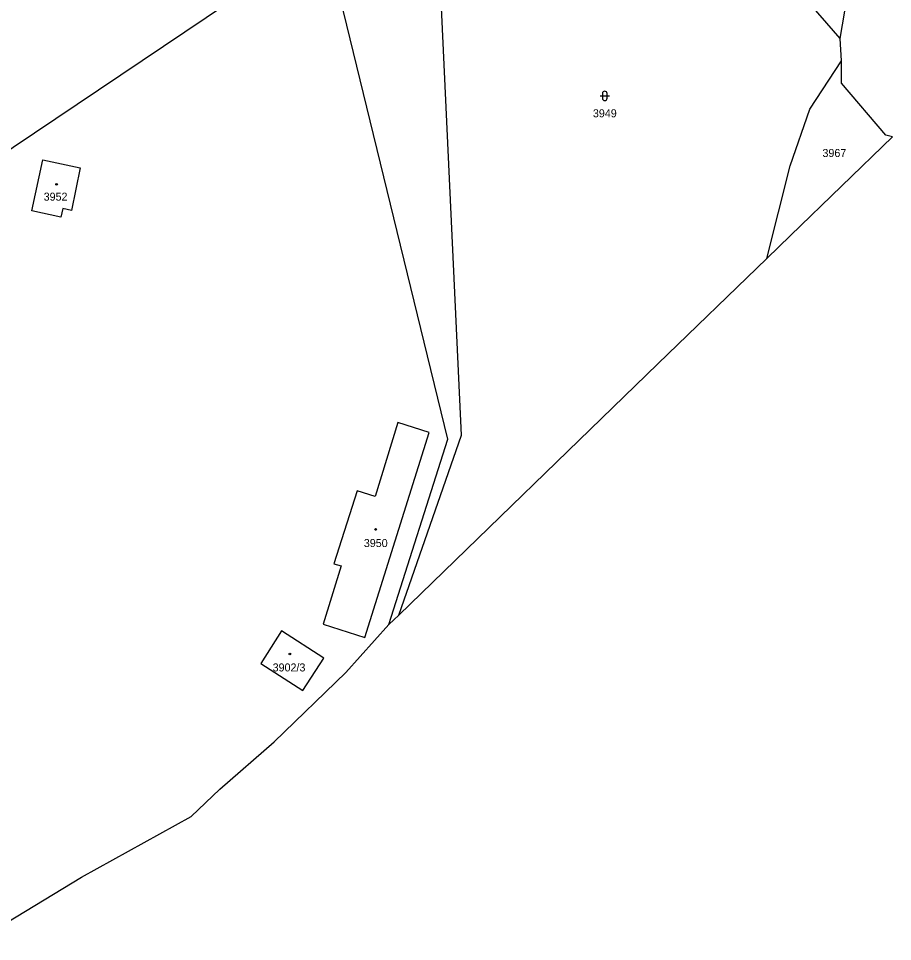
# Model space of a CAD drawing. Extents: x -869103 to -863415, y -1015889 to -1012477.
# Drawn here: x -867451.5 to -867266, y -1015422.4 to -1015226.4 of the extents above; entities that cross this region are included whole.
import ezdxf

# ---------------------------------------------------------------- set-up
doc = ezdxf.new("R2010")
doc.units = 0
for name, color, linetype in [('Hranice katastralního území', 7, 'Continuous'), ('Hranice parcel', 7, 'Continuous'), ('Parcelní čísla', 7, 'Continuous'), ('Poz předměty', 7, 'Continuous'), ('Značky budov', 7, 'Continuous'), ('Značky kultur', 7, 'Continuous')]:
    doc.layers.add(name, color=color, linetype=linetype)

msp = doc.modelspace()

# ---------------------------------------------------------------- linework, layer by layer
at = {"layer": 'Hranice katastralního území'}
for p, q in [((-867277.08, -1015230.7), (-867274.22, -1015213.59)), ((-867276.8, -1015235.41), (-867277.08, -1015230.7)), ((-867287.62, -1015272.48), (-867266, -1015251.53)), ((-867266, -1015251.53), (-867267.4, -1015251.17)), ((-867292.69, -1015277.39), (-867287.62, -1015272.48)), ((-867372.85, -1015355.13), (-867370.74, -1015353.15)), ((-867382.03, -1015365.33), (-867372.85, -1015355.13)), ((-867438.11, -1015408.76), (-867414.81, -1015395.89)), ((-867460.58, -1015422.42), (-867438.11, -1015408.76))]:
    msp.add_line(p, q, dxfattribs=at)
for points in [[(-867267.4, -1015251.17), (-867276.81, -1015240.18), (-867276.8, -1015235.41)], [(-867370.74, -1015353.15), (-867315.8, -1015299.79), (-867292.69, -1015277.39)], [(-867414.81, -1015395.89), (-867408.77, -1015390.08), (-867397.25, -1015380.05), (-867382.03, -1015365.33)]]:
    msp.add_lwpolyline(points, dxfattribs=at)
at = {"layer": 'Hranice parcel'}
for p, q in [((-867277.08, -1015230.7), (-867302.82, -1015200.9)), ((-867277.08, -1015230.7), (-867274.22, -1015213.59)), ((-867276.8, -1015235.41), (-867277.08, -1015230.7)), ((-867287.62, -1015272.48), (-867266, -1015251.53)), ((-867266, -1015251.53), (-867267.4, -1015251.17)), ((-867442.5, -1015268.65), (-867448.66, -1015267.3)), ((-867292.69, -1015277.39), (-867287.62, -1015272.48)), ((-867372.85, -1015355.13), (-867360.38, -1015315.78)), ((-867372.85, -1015355.13), (-867370.74, -1015353.15)), ((-867382.03, -1015365.33), (-867372.85, -1015355.13)), ((-867438.11, -1015408.76), (-867414.81, -1015395.89)), ((-867460.58, -1015422.42), (-867438.11, -1015408.76))]:
    msp.add_line(p, q, dxfattribs=at)
for points in [[(-867360.38, -1015315.78), (-867385.38, -1015212.96), (-867363.24, -1015190.79)], [(-867370.74, -1015353.15), (-867357.43, -1015314.9), (-867363.24, -1015190.79)], [(-867292.69, -1015277.39), (-867287.7, -1015257.7), (-867283.58, -1015245.67), (-867276.8, -1015235.41)], [(-867267.4, -1015251.17), (-867276.81, -1015240.18), (-867276.8, -1015235.41)], [(-867448.66, -1015267.3), (-867446.34, -1015256.41), (-867438.37, -1015258.11), (-867440.2, -1015267.19), (-867442.09, -1015266.77), (-867442.5, -1015268.65)], [(-867370.74, -1015353.15), (-867315.8, -1015299.79), (-867292.69, -1015277.39)], [(-867382.99, -1015342.68), (-867386.83, -1015355.05), (-867377.95, -1015357.85), (-867364.31, -1015314.36), (-867371, -1015312.23), (-867375.79, -1015327.93), (-867379.59, -1015326.71), (-867384.55, -1015342.2), (-867382.99, -1015342.68)], [(-867386.67, -1015362.23), (-867395.63, -1015356.42), (-867400.05, -1015363.42)], [(-867400.05, -1015363.42), (-867391.13, -1015369.11), (-867386.67, -1015362.23)], [(-867414.81, -1015395.89), (-867408.77, -1015390.08), (-867397.25, -1015380.05), (-867382.03, -1015365.33)]]:
    msp.add_lwpolyline(points, dxfattribs=at)
at = {"layer": 'Poz předměty'}
msp.add_lwpolyline([(-867539.04, -1015304.57), (-867511.06, -1015291.88), (-867500.45, -1015287.91), (-867466.24, -1015262.87), (-867398.05, -1015217.05), (-867367.37, -1015183.51)], dxfattribs=at)
at = {"layer": 'Značky budov'}
for centre in [(-867443.39, -1015261.63), (-867375.69, -1015334.92), (-867393.88, -1015361.36)]:
    msp.add_circle(centre, 0.175, dxfattribs=at)
at = {"layer": 'Značky kultur'}
for p, q in [((-867328.07, -1015242.86), (-867326.07, -1015242.86)), ((-867327.57, -1015242.36), (-867327.57, -1015243.36)), ((-867326.57, -1015243.36), (-867326.57, -1015242.36))]:
    msp.add_line(p, q, dxfattribs=at)
for centre, start, end in [((-867327.07, -1015242.36), 0, 180), ((-867327.07, -1015243.36), 180, 359.9879)]:
    msp.add_arc(centre, 0.5, start, end, dxfattribs=at)

# ---------------------------------------------------------------- texts
at = {"layer": 'Parcelní čísla'}
for s, p in [('3949', (-867329.58, -1015247.41)), ('3967', (-867280.87, -1015255.84)), ('3952', (-867446.13, -1015265.11)), ('3950', (-867378.19, -1015338.66)), ('3902/3', (-867397.54, -1015365.07))]:
    msp.add_text(s, height=1.7, dxfattribs=at).set_placement(p)

doc.saveas('drawing.dxf')
